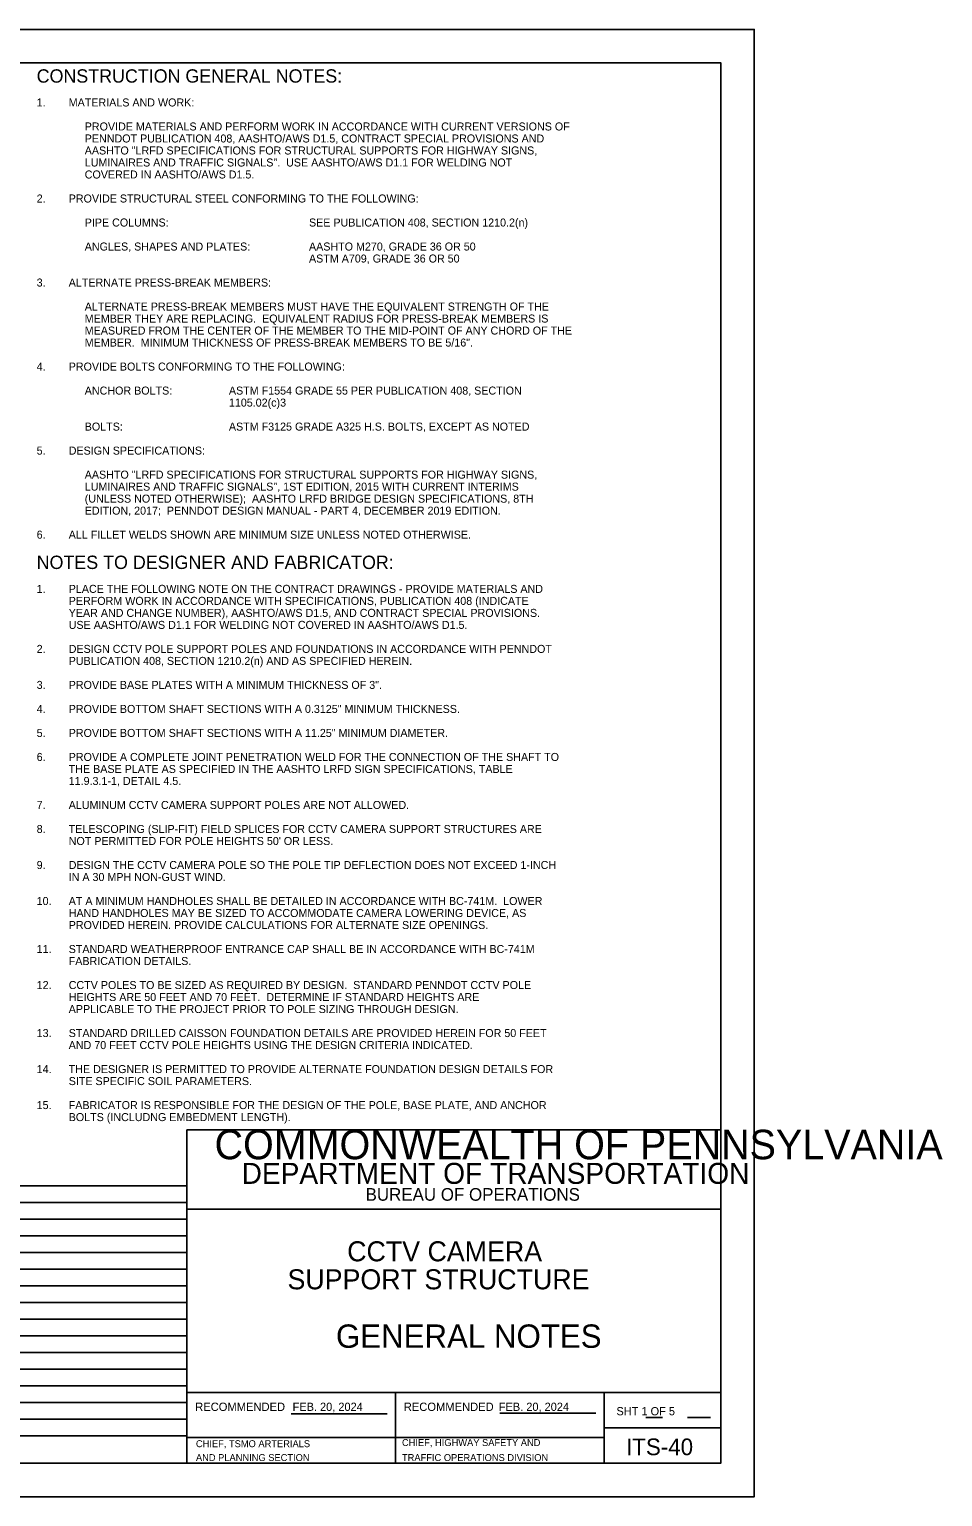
# Model space of a CAD drawing. Extents: x 1299105.1 to 1299141.9, y 239690 to 239712.
# Drawn here: x 1299128.23 to 1299141.91, y 239689.98 to 239711.98 of the extents above; entities that cross this region are included whole.
import ezdxf

# ---------------------------------------------------------------- set-up
doc = ezdxf.new("R2010")
doc.units = 0
for name, color, linetype in [('1', 7, 'Continuous'), ('2', 7, 'Continuous'), ('DIM TXT', 7, 'Continuous'), ('GS_plotshape_p', 7, 'Continuous'), ('Level 1', 7, 'Continuous'), ('PTEXT', 7, 'Continuous')]:
    doc.layers.add(name, color=color, linetype=linetype)

msp = doc.modelspace()

# ---------------------------------------------------------------- linework, layer by layer
at = {"layer": '1'}
for p, q in [((1299132.153, 239691.227), (1299133.59, 239691.227)), ((1299135.278, 239691.236), (1299136.715, 239691.236)), ((1299130.59, 239690.873), (1299133.715, 239690.873))]:
    msp.add_line(p, q, dxfattribs=at)
at = {"layer": 'DIM TXT'}
for p, q in [((1299122.492, 239694.646), (1299130.59, 239694.646)), ((1299122.492, 239694.396), (1299130.59, 239694.396)), ((1299122.492, 239694.146), (1299130.59, 239694.146)), ((1299122.492, 239693.896), (1299130.59, 239693.896)), ((1299122.492, 239693.646), (1299130.59, 239693.646)), ((1299122.492, 239693.396), (1299130.59, 239693.396)), ((1299122.492, 239693.146), (1299130.59, 239693.146)), ((1299122.492, 239692.896), (1299130.59, 239692.896)), ((1299122.492, 239692.646), (1299130.59, 239692.646)), ((1299122.492, 239692.396), (1299130.59, 239692.396)), ((1299122.492, 239692.146), (1299130.59, 239692.146)), ((1299122.492, 239691.896), (1299130.59, 239691.896)), ((1299122.492, 239691.646), (1299130.59, 239691.646)), ((1299122.492, 239691.396), (1299130.59, 239691.396)), ((1299122.492, 239691.146), (1299130.59, 239691.146)), ((1299122.492, 239690.896), (1299130.59, 239690.896))]:
    msp.add_line(p, q, dxfattribs=at)
at = {"layer": 'GS_plotshape_p'}
msp.add_lwpolyline([(1299105.09, 239711.984), (1299139.09, 239711.984), (1299139.09, 239689.984), (1299105.09, 239689.984)], close=True, dxfattribs=at)
at = {"layer": 'Level 1'}
for p, q in [((1299130.59, 239691.547), (1299138.59, 239691.547)), ((1299133.715, 239690.484), (1299133.715, 239691.547)), ((1299136.84, 239690.484), (1299136.84, 239691.547)), ((1299137.465, 239691.172), (1299137.715, 239691.172)), ((1299138.09, 239691.172), (1299138.434, 239691.172)), ((1299136.84, 239691.015), (1299138.59, 239691.015)), ((1299133.715, 239690.873), (1299136.84, 239690.873))]:
    msp.add_line(p, q, dxfattribs=at)
for points in [[(1299138.59, 239690.484), (1299106.59, 239690.484), (1299106.59, 239711.484), (1299138.59, 239711.484)], [(1299130.59, 239690.484), (1299138.59, 239690.484), (1299138.59, 239695.484), (1299130.59, 239695.484)], [(1299130.59, 239695.484), (1299138.59, 239695.484), (1299138.59, 239694.297), (1299130.59, 239694.297)]]:
    msp.add_lwpolyline(points, close=True, dxfattribs=at)

# ---------------------------------------------------------------- texts
at = {"layer": '1'}
for s, height, p in [('COMMONWEALTH OF PENNSYLVANIA', 0.44223, (1299131.005, 239695.043)), ('DEPARTMENT OF TRANSPORTATION', 0.31514, (1299131.41, 239694.674)), ('BUREAU OF OPERATIONS', 0.18955, (1299133.268, 239694.421)), ('RECOMMENDED', 0.125, (1299130.715, 239691.269)), ('FEB. 20, 2024', 0.12303, (1299132.174, 239691.27)), ('RECOMMENDED', 0.125, (1299133.84, 239691.269)), ('FEB. 20, 2024', 0.12303, (1299135.264, 239691.27)), ('CHIEF, TSMO ARTERIALS ', 0.10417, (1299130.726, 239690.726)), ('CHIEF, HIGHWAY SAFETY AND ', 0.10417, (1299133.813, 239690.743)), ('AND PLANNING SECTION', 0.10417, (1299130.726, 239690.518)), ('TRAFFIC OPERATIONS DIVISION', 0.10417, (1299133.813, 239690.518))]:
    msp.add_text(s, height=height, dxfattribs=at).set_placement(p)
at = {"layer": '2'}
msp.add_text('SHT 1 OF 5', height=0.123, dxfattribs=at).set_placement((1299137.026, 239691.204))
at = {"layer": 'DIM TXT'}
for s, height, p in [('CONSTRUCTION GENERAL NOTES:', 0.2, (1299128.34, 239711.185)), ('1.', 0.12, (1299128.34, 239710.828)), ('MATERIALS AND WORK:', 0.12, (1299128.82, 239710.828)), ('PROVIDE MATERIALS AND PERFORM WORK IN ACCORDANCE WITH CURRENT VERSIONS OF ', 0.12, (1299129.06, 239710.468)), ('PENNDOT PUBLICATION 408, AASHTO/AWS D1.5, CONTRACT SPECIAL PROVISIONS AND ', 0.12, (1299129.06, 239710.288)), ('AASHTO "LRFD SPECIFICATIONS FOR STRUCTURAL SUPPORTS FOR HIGHWAY SIGNS, ', 0.12, (1299129.06, 239710.108)), ('LUMINAIRES AND TRAFFIC SIGNALS".  USE AASHTO/AWS D1.1 FOR WELDING NOT ', 0.12, (1299129.06, 239709.928)), ('COVERED IN AASHTO/AWS D1.5.', 0.12, (1299129.06, 239709.748)), ('2.', 0.12, (1299128.34, 239709.388)), ('PROVIDE STRUCTURAL STEEL CONFORMING TO THE FOLLOWING:', 0.12, (1299128.82, 239709.388)), ('PIPE COLUMNS:', 0.12, (1299129.06, 239709.028)), ('SEE PUBLICATION 408, SECTION 1210.2(n)', 0.12, (1299132.42, 239709.028)), ('ANGLES, SHAPES AND PLATES:', 0.12, (1299129.06, 239708.668)), ('AASHTO M270, GRADE 36 OR 50', 0.12, (1299132.42, 239708.668)), ('ASTM A709, GRADE 36 OR 50', 0.12, (1299132.42, 239708.488)), ('3.', 0.12, (1299128.34, 239708.128)), ('ALTERNATE PRESS-BREAK MEMBERS:', 0.12, (1299128.82, 239708.128)), ('ALTERNATE PRESS-BREAK MEMBERS MUST HAVE THE EQUIVALENT STRENGTH OF THE ', 0.12, (1299129.06, 239707.768)), ('MEMBER THEY ARE REPLACING.  EQUIVALENT RADIUS FOR PRESS-BREAK MEMBERS IS ', 0.12, (1299129.06, 239707.588)), ('MEASURED FROM THE CENTER OF THE MEMBER TO THE MID-POINT OF ANY CHORD OF THE ', 0.12, (1299129.06, 239707.408)), ('MEMBER.  MINIMUM THICKNESS OF PRESS-BREAK MEMBERS TO BE 5/16".', 0.12, (1299129.06, 239707.228)), ('4.', 0.12, (1299128.34, 239706.868)), ('PROVIDE BOLTS CONFORMING TO THE FOLLOWING:', 0.12, (1299128.82, 239706.868)), ('ANCHOR BOLTS:', 0.12, (1299129.06, 239706.508)), ('ASTM F1554 GRADE 55 PER PUBLICATION 408, SECTION ', 0.12, (1299131.22, 239706.508)), ('1105.02(c)3', 0.12, (1299131.22, 239706.328)), ('BOLTS:', 0.12, (1299129.06, 239705.968)), ('ASTM F3125 GRADE A325 H.S. BOLTS, EXCEPT AS NOTED', 0.12, (1299131.22, 239705.968)), ('5.', 0.12, (1299128.34, 239705.608)), ('DESIGN SPECIFICATIONS:', 0.12, (1299128.82, 239705.608)), ('AASHTO "LRFD SPECIFICATIONS FOR STRUCTURAL SUPPORTS FOR HIGHWAY SIGNS, ', 0.12, (1299129.06, 239705.248)), ('LUMINAIRES AND TRAFFIC SIGNALS", 1ST EDITION, 2015 WITH CURRENT INTERIMS ', 0.12, (1299129.06, 239705.068)), ('(UNLESS NOTED OTHERWISE);  AASHTO LRFD BRIDGE DESIGN SPECIFICATIONS, 8TH ', 0.12, (1299129.06, 239704.888)), ('EDITION, 2017;  PENNDOT DESIGN MANUAL - PART 4, DECEMBER 2019 EDITION.', 0.12, (1299129.06, 239704.708)), ('6.', 0.12, (1299128.34, 239704.348)), ('ALL FILLET WELDS SHOWN ARE MINIMUM SIZE UNLESS NOTED OTHERWISE.', 0.12, (1299128.82, 239704.348)), ('NOTES TO DESIGNER AND FABRICATOR:', 0.2, (1299128.34, 239703.893)), ('1.', 0.12, (1299128.34, 239703.535)), ('PLACE THE FOLLOWING NOTE ON THE CONTRACT DRAWINGS - PROVIDE MATERIALS AND ', 0.12, (1299128.82, 239703.535)), ('PERFORM WORK IN ACCORDANCE WITH SPECIFICATIONS, PUBLICATION 408 (INDICATE ', 0.12, (1299128.82, 239703.355)), ('YEAR AND CHANGE NUMBER), AASHTO/AWS D1.5, AND CONTRACT SPECIAL PROVISIONS.  ', 0.12, (1299128.82, 239703.175)), ('USE AASHTO/AWS D1.1 FOR WELDING NOT COVERED IN AASHTO/AWS D1.5.', 0.12, (1299128.82, 239702.995)), ('2.', 0.12, (1299128.34, 239702.635)), ('DESIGN CCTV POLE SUPPORT POLES AND FOUNDATIONS IN ACCORDANCE WITH PENNDOT ', 0.12, (1299128.82, 239702.635)), ('PUBLICATION 408, SECTION 1210.2(n) AND AS SPECIFIED HEREIN.', 0.12, (1299128.82, 239702.455)), ('3.', 0.12, (1299128.34, 239702.095)), ('PROVIDE BASE PLATES WITH A MINIMUM THICKNESS OF 3".', 0.12, (1299128.82, 239702.095)), ('4.', 0.12, (1299128.34, 239701.735)), ('PROVIDE BOTTOM SHAFT SECTIONS WITH A 0.3125" MINIMUM THICKNESS.', 0.12, (1299128.82, 239701.735)), ('5.', 0.12, (1299128.34, 239701.375)), ('PROVIDE BOTTOM SHAFT SECTIONS WITH A 11.25" MINIMUM DIAMETER.', 0.12, (1299128.82, 239701.375)), ('6.', 0.12, (1299128.34, 239701.015)), ('PROVIDE A COMPLETE JOINT PENETRATION WELD FOR THE CONNECTION OF THE SHAFT TO ', 0.12, (1299128.82, 239701.015)), ('THE BASE PLATE AS SPECIFIED IN THE AASHTO LRFD SIGN SPECIFICATIONS, TABLE ', 0.12, (1299128.82, 239700.835)), ('11.9.3.1-1, DETAIL 4.5.', 0.12, (1299128.82, 239700.655)), ('7.', 0.12, (1299128.34, 239700.295)), ('ALUMINUM CCTV CAMERA SUPPORT POLES ARE NOT ALLOWED.', 0.12, (1299128.82, 239700.295)), ('8.', 0.12, (1299128.34, 239699.935)), ('TELESCOPING (SLIP-FIT) FIELD SPLICES FOR CCTV CAMERA SUPPORT STRUCTURES ARE ', 0.12, (1299128.82, 239699.935)), ("NOT PERMITTED FOR POLE HEIGHTS 50' OR LESS.", 0.12, (1299128.82, 239699.755)), ('9.', 0.12, (1299128.34, 239699.395)), ('DESIGN THE CCTV CAMERA POLE SO THE POLE TIP DEFLECTION DOES NOT EXCEED 1-INCH ', 0.12, (1299128.82, 239699.395)), ('IN A 30 MPH NON-GUST WIND.', 0.12, (1299128.82, 239699.215)), ('10.', 0.12, (1299128.34, 239698.855)), ('AT A MINIMUM HANDHOLES SHALL BE DETAILED IN ACCORDANCE WITH BC-741M.  LOWER ', 0.12, (1299128.82, 239698.855)), ('HAND HANDHOLES MAY BE SIZED TO ACCOMMODATE CAMERA LOWERING DEVICE, AS ', 0.12, (1299128.82, 239698.675)), ('PROVIDED HEREIN. PROVIDE CALCULATIONS FOR ALTERNATE SIZE OPENINGS.', 0.12, (1299128.82, 239698.495)), ('11.', 0.12, (1299128.34, 239698.135)), ('STANDARD WEATHERPROOF ENTRANCE CAP SHALL BE IN ACCORDANCE WITH BC-741M ', 0.12, (1299128.82, 239698.135)), ('FABRICATION DETAILS.', 0.12, (1299128.82, 239697.955)), ('12.', 0.12, (1299128.34, 239697.595)), ('CCTV POLES TO BE SIZED AS REQUIRED BY DESIGN.  STANDARD PENNDOT CCTV POLE ', 0.12, (1299128.82, 239697.595)), ('HEIGHTS ARE 50 FEET AND 70 FEET.  DETERMINE IF STANDARD HEIGHTS ARE ', 0.12, (1299128.82, 239697.415)), ('APPLICABLE TO THE PROJECT PRIOR TO POLE SIZING THROUGH DESIGN.', 0.12, (1299128.82, 239697.235)), ('13.', 0.12, (1299128.34, 239696.875)), ('STANDARD DRILLED CAISSON FOUNDATION DETAILS ARE PROVIDED HEREIN FOR 50 FEET ', 0.12, (1299128.82, 239696.875)), ('AND 70 FEET CCTV POLE HEIGHTS USING THE DESIGN CRITERIA INDICATED.', 0.12, (1299128.82, 239696.695)), ('14.', 0.12, (1299128.34, 239696.335)), ('THE DESIGNER IS PERMITTED TO PROVIDE ALTERNATE FOUNDATION DESIGN DETAILS FOR ', 0.12, (1299128.82, 239696.335)), ('SITE SPECIFIC SOIL PARAMETERS.', 0.12, (1299128.82, 239696.155)), ('15.', 0.12, (1299128.34, 239695.795)), ('FABRICATOR IS RESPONSIBLE FOR THE DESIGN OF THE POLE, BASE PLATE, AND ANCHOR ', 0.12, (1299128.82, 239695.795)), ('BOLTS (INCLUDNG EMBEDMENT LENGTH).', 0.12, (1299128.82, 239695.615))]:
    msp.add_text(s, height=height, dxfattribs=at).set_placement(p)
at = {"layer": 'PTEXT'}
for s, height, p in [('CCTV CAMERA', 0.3, (1299132.992, 239693.513)), ('SUPPORT STRUCTURE', 0.3, (1299132.098, 239693.093)), ('GENERAL NOTES', 0.35, (1299132.824, 239692.216)), ('ITS-40', 0.25, (1299137.171, 239690.606))]:
    msp.add_text(s, height=height, dxfattribs=at).set_placement(p)

doc.saveas('drawing.dxf')
